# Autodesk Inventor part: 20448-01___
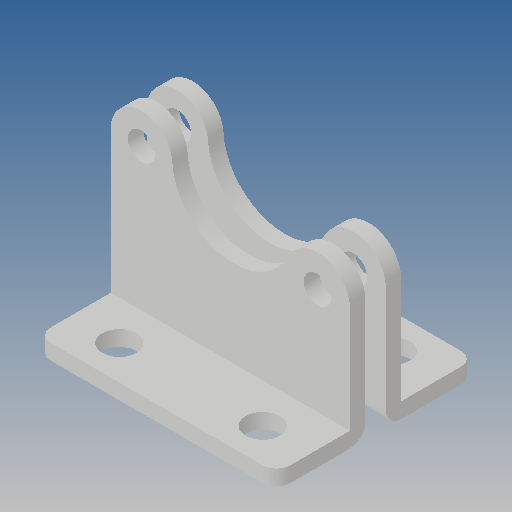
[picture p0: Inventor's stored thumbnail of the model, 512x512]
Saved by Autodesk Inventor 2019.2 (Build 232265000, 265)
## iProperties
Created: 2010-06
Part Number: 20448-01___
Material: Ogólny
Document SubType Name: Modeling
Designer: CADENGINEERING4
Density: 1 g/cm^3
Appearance: Domyślna
Author: CADENGINEERING4
Revision Number: ANY
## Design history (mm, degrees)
feature "NONE"
feature "NONE:1"
node "Bryła1"
node "Bryła2"
